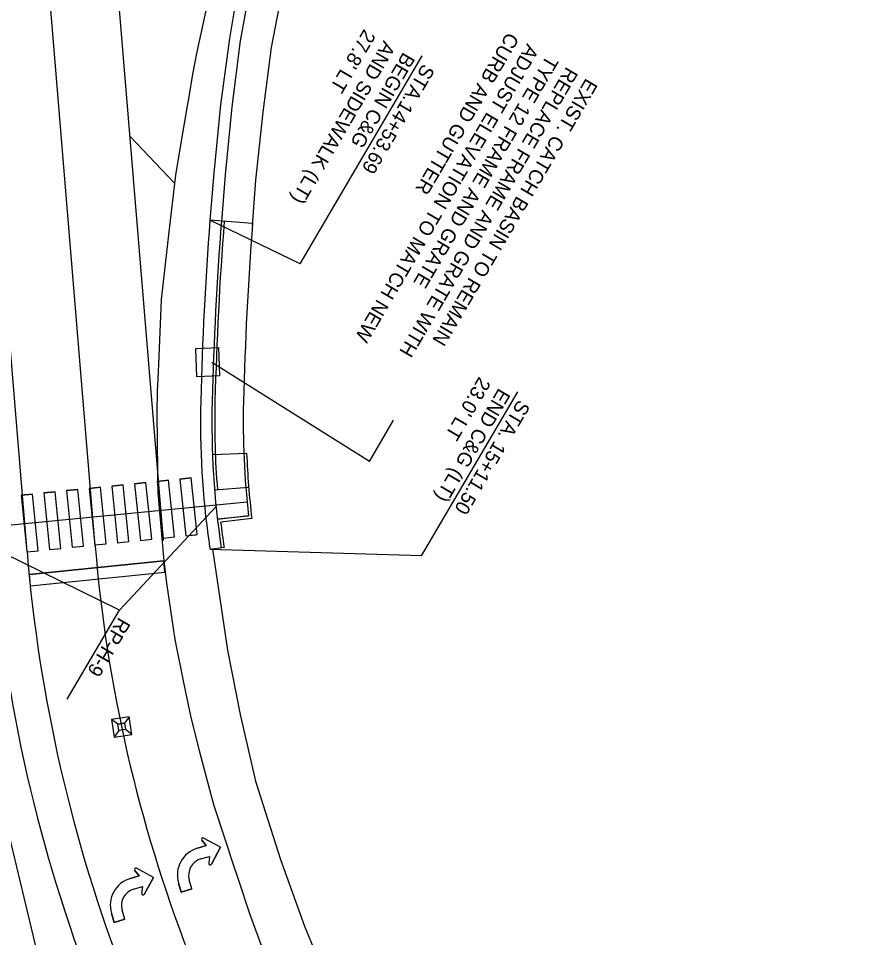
# Model space of a CAD drawing. Extents: x 1730210 to 1732101, y 650763 to 653427.
# Drawn here: x 1730520.8 to 1730667, y 652788.8 to 652950.2 of the extents above; entities that cross this region are included whole.
import ezdxf

# ---------------------------------------------------------------- set-up
doc = ezdxf.new("R2010")
doc.units = 0
for name, color, linetype in [('DESIGN - ROW - Slope Lines', 7, 'Continuous'), ('DESIGN - SCRATCH - User 2', 7, 'Continuous'), ('DESIGN - TRAFFIC CONTROL PERMANENT - Pavement Marking', 7, 'Continuous'), ('DESIGN - TRANSPORTATION - Curb Gutter and Sidewalk', 7, 'Continuous'), ('DESIGN - TRANSPORTATION - Edge of Traveled Way', 7, 'Continuous'), ('DESIGN - TRANSPORTATION - Shoulder Lines', 7, 'Continuous'), ('DESIGN - TRANSPORTATION - Text', 7, 'Continuous'), ('FUNCTIONAL - TRANSPORTATION - Preliminary Edge of Traveled Way', 7, 'Continuous'), ('SURVEY - DRAINAGE - Storm Sewer', 7, 'Continuous'), ('SURVEY - TRANSPORTATION - Features', 7, 'Continuous')]:
    doc.layers.add(name, color=color, linetype=linetype)

msp = doc.modelspace()

# ---------------------------------------------------------------- linework, layer by layer
at = {"layer": 'DESIGN - ROW - Slope Lines'}
msp.add_line((1730517.89, 652812.05), (1730530.41, 652759.65), dxfattribs=at)
at = {"layer": 'DESIGN - SCRATCH - User 2'}
msp.add_lwpolyline([(1730553.8, 652952.1), (1730552.12, 652944.29), (1730551.36, 652940.37), (1730550.69, 652936.43), (1730550.36, 652934.47), (1730549.02, 652926.59), (1730548.34, 652922.65), (1730547.19, 652912.74), (1730545.82, 652900.84), (1730545.4, 652890.87), (1730545.23, 652886.88), (1730545.15, 652884.89), (1730545.09, 652880.9), (1730545.17, 652870.91), (1730545.23, 652866.92), (1730546.28, 652854.99), (1730546.78, 652851.03), (1730547.95, 652843.13), (1730548.24, 652841.16), (1730549.79, 652833.32), (1730551.04, 652827.47), (1730552.53, 652821.67), (1730554.53, 652813.94), (1730555.08, 652812.02), (1730556.95, 652806.33), (1730557.57, 652804.43), (1730558.2, 652802.54), (1730559.44, 652798.74), (1730561.33, 652793.06), (1730564.07, 652785.56)], dxfattribs=at)
at = {"layer": 'DESIGN - TRAFFIC CONTROL PERMANENT - Pavement Marking'}
for p, q in [((1730534.26, 652857.53), (1730525.83, 652959.78)), ((1730546.22, 652858.52), (1730537.78, 652960.76)), ((1730540.37, 652929.48), (1730548.18, 652921.25)), ((1730549.12, 652869.33), (1730551.11, 652869.53)), ((1730533.21, 652867.7), (1730535.2, 652867.91)), ((1730537.19, 652868.11), (1730539.18, 652868.31)), ((1730541.17, 652868.52), (1730543.16, 652868.72)), ((1730545.15, 652868.92), (1730547.13, 652869.12)), ((1730521.27, 652866.49), (1730523.26, 652866.69)), ((1730525.25, 652866.89), (1730527.24, 652867.1)), ((1730529.23, 652867.3), (1730531.22, 652867.5)), ((1730550.14, 652859.38), (1730552.13, 652859.58)), ((1730550.14, 652859.38), (1730551.89, 652859.56)), ((1730534.22, 652857.76), (1730536.21, 652857.96)), ((1730538.2, 652858.16), (1730540.19, 652858.36)), ((1730542.18, 652858.57), (1730544.17, 652858.77)), ((1730546.16, 652858.97), (1730548.15, 652859.17)), ((1730522.28, 652856.54), (1730524.27, 652856.74)), ((1730526.26, 652856.95), (1730528.25, 652857.15)), ((1730530.24, 652857.35), (1730532.23, 652857.55)), ((1730522.66, 652852.56), (1730546.28, 652854.96)), ((1730522.66, 652852.56), (1730546.28, 652854.96)), ((1730556.26, 652804.71), (1730553.29, 652806.32)), ((1730556.26, 652804.71), (1730553.29, 652806.32)), ((1730553.75, 652805), (1730552.2, 652804.54)), ((1730552.2, 652804.54), (1730553.75, 652805)), ((1730552.98, 652805.95), (1730553.75, 652805)), ((1730553.75, 652805), (1730552.98, 652805.95)), ((1730554.64, 652801.74), (1730556.26, 652804.71)), ((1730556.26, 652804.71), (1730554.64, 652801.74)), ((1730552.76, 652802.65), (1730554.31, 652803.11)), ((1730552.76, 652802.65), (1730554.31, 652803.11)), ((1730554.31, 652803.11), (1730554.18, 652801.89)), ((1730554.31, 652803.11), (1730554.18, 652801.89)), ((1730541.21, 652800.65), (1730541.99, 652799.69)), ((1730541.99, 652799.69), (1730541.21, 652800.65)), ((1730544.49, 652799.41), (1730541.52, 652801.02)), ((1730544.49, 652799.41), (1730541.52, 652801.02)), ((1730541.99, 652799.69), (1730540.43, 652799.24)), ((1730540.43, 652799.24), (1730541.99, 652799.69)), ((1730542.88, 652796.44), (1730544.49, 652799.41)), ((1730544.49, 652799.41), (1730542.88, 652796.44)), ((1730548.88, 652798.43), (1730549.35, 652796.82)), ((1730549.35, 652796.82), (1730548.88, 652798.43)), ((1730551.24, 652797.38), (1730550.77, 652798.98)), ((1730551.24, 652797.38), (1730550.77, 652798.98)), ((1730540.99, 652797.35), (1730542.54, 652797.81)), ((1730540.99, 652797.35), (1730542.54, 652797.81)), ((1730542.54, 652797.81), (1730542.41, 652796.58)), ((1730542.54, 652797.81), (1730542.41, 652796.58)), ((1730549.35, 652796.82), (1730551.24, 652797.38)), ((1730551.24, 652797.38), (1730549.35, 652796.82)), ((1730539.47, 652792.07), (1730539, 652793.68)), ((1730539.47, 652792.07), (1730539, 652793.68)), ((1730537.11, 652793.12), (1730537.59, 652791.52)), ((1730537.59, 652791.52), (1730537.11, 652793.12)), ((1730537.59, 652791.52), (1730539.47, 652792.07)), ((1730539.47, 652792.07), (1730537.59, 652791.52))]:
    msp.add_line(p, q, dxfattribs=at)
for points in [[(1730549.12, 652869.33), (1730550.14, 652859.38), (1730552.13, 652859.58), (1730551.11, 652869.53)], [(1730533.21, 652867.7), (1730534.22, 652857.76), (1730536.21, 652857.96), (1730535.2, 652867.91)], [(1730537.19, 652868.11), (1730538.2, 652858.16), (1730540.19, 652858.36), (1730539.18, 652868.31)], [(1730541.17, 652868.52), (1730542.18, 652858.57), (1730544.17, 652858.77), (1730543.16, 652868.72)], [(1730545.15, 652868.92), (1730546.16, 652858.97), (1730548.15, 652859.17), (1730547.13, 652869.12)], [(1730521.27, 652866.49), (1730522.28, 652856.54), (1730524.27, 652856.74), (1730523.26, 652866.69)], [(1730525.25, 652866.89), (1730526.26, 652856.95), (1730528.25, 652857.15), (1730527.24, 652867.1)], [(1730529.23, 652867.3), (1730530.24, 652857.35), (1730532.23, 652857.55), (1730531.22, 652867.5)], [(1730522.66, 652852.56), (1730522.87, 652850.57), (1730546.49, 652852.97), (1730546.28, 652854.96)], [(1730539.39, 652826.49), (1730539.56, 652825.35), (1730538.38, 652825.17), (1730538.21, 652826.3)]]:
    msp.add_lwpolyline(points, close=True, dxfattribs=at)
for points in [[(1730540.23, 652827.62), (1730537.12, 652827.15), (1730537.59, 652824.04), (1730540.7, 652824.51), (1730540.23, 652827.62)], [(1730540.23, 652827.62), (1730539.39, 652826.49), (1730538.21, 652826.3), (1730537.12, 652827.15)], [(1730540.7, 652824.51), (1730539.56, 652825.35), (1730538.38, 652825.17), (1730537.59, 652824.04)]]:
    msp.add_lwpolyline(points, dxfattribs=at)
for centre, radius, start, end in [((1732146.89, 652178.93), 1845.51, 143.31109, 155.90666), ((1730790.39, 652878.67), 257, 184.7177, 201.1154), ((1730553.17, 652806.11), 0.246, 61.4689, 218.9172), ((1730553.17, 652806.11), 0.246, 61.4689, 218.9172), ((1730553.6, 652799.82), 4.92, 106.4689, 196.4689), ((1730553.6, 652799.82), 4.92, 106.4689, 196.4689), ((1730553.6, 652799.82), 2.95, 106.4689, 196.4689), ((1730553.6, 652799.82), 2.95, 106.4689, 196.4689), ((1730554.43, 652801.86), 0.246, 173.9758, 331.4689), ((1730554.43, 652801.86), 0.246, 173.9758, 331.4689), ((1730541.4, 652800.8), 0.246, 61.4689, 218.9172), ((1730541.4, 652800.8), 0.246, 61.4689, 218.9172), ((1730541.83, 652794.52), 4.92, 106.4689, 196.4689), ((1730541.83, 652794.52), 4.92, 106.4689, 196.4689), ((1730541.83, 652794.52), 2.95, 106.4689, 196.4689), ((1730541.83, 652794.52), 2.95, 106.4689, 196.4689), ((1730542.66, 652796.56), 0.246, 173.9758, 331.4689), ((1730542.66, 652796.56), 0.246, 173.9758, 331.4689)]:
    msp.add_arc(centre, radius, start, end, dxfattribs=at)
at = {"layer": 'DESIGN - TRANSPORTATION - Curb Gutter and Sidewalk'}
for p, q in [((1730561.88, 652914.18), (1730554.4, 652914.76)), ((1730560.84, 652873.84), (1730554.84, 652873.61)), ((1730561.19, 652867.87), (1730555.21, 652867.39)), ((1730555.71, 652862.32), (1730561.16, 652862.86)), ((1730561.18, 652862.86), (1730555.72, 652862.22)), ((1730561.74, 652862.42), (1730556.28, 652861.78)), ((1730556.88, 652857.33), (1730554.4, 652856.96))]:
    msp.add_line(p, q, dxfattribs=at)
for centre, radius, start, end in [((1731162.59, 652867.76), 610, 175.58059, 178.56365), ((1731162.59, 652867.76), 608, 175.58059, 178.56365), ((1731162.59, 652867.76), 607.5, 175.58059, 178.56365), ((1731162.59, 652867.76), 602.5, 175.58059, 178.56365), ((1730702.73, 652879.29), 150, 178.5662, 188.1098), ((1730702.73, 652879.29), 148, 178.5662, 188.5523), ((1730702.73, 652879.29), 147.5, 178.5662, 184.6125), ((1730702.73, 652879.29), 142.5, 178.5662, 186.6229), ((1730702.73, 652879.29), 142, 182.1999, 186.8247), ((1730702.73, 652879.29), 147.5, 186.8172, 188.5653), ((1730891.7, 652906.22), 340.87, 188.1098, 188.3084)]:
    msp.add_arc(centre, radius, start, end, dxfattribs=at)
at = {"layer": 'DESIGN - TRANSPORTATION - Edge of Traveled Way'}
msp.add_line((1730522.3, 652856.54), (1730516.35, 652928.65), dxfattribs=at)
msp.add_lwpolyline([(1730553.8, 652952.1), (1730552.12, 652944.29), (1730551.36, 652940.37), (1730550.69, 652936.43), (1730550.36, 652934.47), (1730549.02, 652926.59), (1730548.34, 652922.65), (1730547.19, 652912.74), (1730545.82, 652900.84), (1730545.4, 652890.87), (1730545.23, 652886.88), (1730545.15, 652884.89), (1730545.09, 652880.9), (1730545.17, 652870.91), (1730545.23, 652866.92), (1730546.28, 652854.99), (1730546.78, 652851.03), (1730547.95, 652843.13), (1730548.24, 652841.16), (1730549.79, 652833.32), (1730551.04, 652827.47), (1730552.53, 652821.67), (1730554.53, 652813.94), (1730555.08, 652812.02), (1730556.95, 652806.33), (1730557.57, 652804.43), (1730558.2, 652802.54), (1730559.44, 652798.74), (1730561.33, 652793.06), (1730564.07, 652785.56)], dxfattribs=at)
msp.add_arc((1730790.39, 652878.67), 269, 184.7177, 201.1154, dxfattribs=at)
at = {"layer": 'DESIGN - TRANSPORTATION - Shoulder Lines'}
msp.add_arc((1730790.39, 652878.67), 275, 184.7177, 201.1154, dxfattribs=at)
at = {"layer": 'DESIGN - TRANSPORTATION - Text'}
for p, q in [((1730570.25, 652907.13), (1730591.65, 652943.61)), ((1730591.52, 652855.88), (1730608.4, 652884.63)), ((1730582.37, 652872.41), (1730586.63, 652879.66)), ((1730529.35, 652830.67), (1730538.53, 652846.32))]:
    msp.add_line(p, q, dxfattribs=at)
for points in [[(1730570.25, 652907.13), (1730554.4, 652914.76)], [(1730582.37, 652872.41), (1730554.74, 652889.8)], [(1730538.53, 652846.32), (1730555.47, 652864.51)], [(1730538.53, 652846.32), (1730514.68, 652858)], [(1730591.52, 652855.88), (1730554.4, 652856.96)]]:
    msp.add_lwpolyline(points, dxfattribs=at)
at = {"layer": 'FUNCTIONAL - TRANSPORTATION - Preliminary Edge of Traveled Way'}
msp.add_line((1730507.46, 652860.09), (1730560.92, 652865.34), dxfattribs=at)
at = {"layer": 'SURVEY - DRAINAGE - Storm Sewer'}
msp.add_line((1730554, 652889.84), (1730554, 652889.84), dxfattribs=at)
msp.add_lwpolyline([(1730551.9, 652892.26), (1730555.9, 652892.42), (1730556.09, 652887.42), (1730552.09, 652887.26), (1730551.9, 652892.26)], dxfattribs=at)
at = {"layer": 'SURVEY - TRANSPORTATION - Features'}
for points in [[(1730592.04, 653052.85), (1730591.18, 653050.64), (1730586.09, 653037.26), (1730578.08, 653014.81), (1730570.43, 652992.33), (1730566.69, 652980.98), (1730563.23, 652969.76), (1730560.07, 652958.21), (1730558.94, 652953.33), (1730557.81, 652946.66), (1730556.25, 652934.99), (1730555.09, 652923.03), (1730554.38, 652914.72)], [(1730593.81, 653052), (1730593.01, 653049.91), (1730587.95, 653036.51), (1730579.97, 653014.12), (1730572.35, 652991.72), (1730568.61, 652980.38), (1730565.18, 652969.25), (1730561.99, 652957.71), (1730560.9, 652952.93), (1730559.72, 652946.25), (1730558.22, 652934.65), (1730557.04, 652922.7), (1730556.4, 652914.49)], [(1730598.78, 653049.61), (1730598.21, 653047.82), (1730593.16, 653034.42), (1730585.23, 653012.19), (1730577.61, 652990.04), (1730573.85, 652978.74), (1730570.46, 652967.88), (1730567.29, 652956.32), (1730565.12, 652945.09), (1730563.69, 652933.72), (1730562.37, 652921.79), (1730561.79, 652913.85)], [(1730554.83, 652857.03), (1730557.5, 652839.27), (1730559.67, 652827.99), (1730562.4, 652816.32), (1730566.77, 652802.56), (1730571, 652790.87), (1730575.24, 652780.51), (1730576.8, 652779.63)]]:
    msp.add_lwpolyline(points, dxfattribs=at)

# ---------------------------------------------------------------- texts
at = {"layer": 'DESIGN - TRANSPORTATION - Text'}
for s, p in [("27.8' LT", (1730581.45, 652948.44)), ('CURB AND GUTTER', (1730606.61, 652947.92)), ('AND SIDEWALK (LT)', (1730584.9, 652946.41)), ('ADJUST ELEVATION TO MATCH NEW', (1730610.06, 652945.89)), ('BEGIN C&G', (1730588.35, 652944.39)), ('STA.14+53.69', (1730591.8, 652942.37)), ('TYPE 12 FRAME AND GRATE', (1730613.51, 652943.87)), ('REPLACE FRAME AND GRATE WITH', (1730616.95, 652941.84)), ('EXIST. CATCH BASIN TO REMAIN', (1730620.4, 652939.82)), ("23.0' LT", (1730601.64, 652887.44)), ('END C&G (LT)', (1730605.09, 652885.42)), ('STA. 15+11.50', (1730608.54, 652883.39)), ('RP-H-9', (1730538.42, 652845.22))]:
    msp.add_text(s, height=2.5, rotation=239.5926, dxfattribs=at).set_placement(p)

doc.saveas('drawing.dxf')
